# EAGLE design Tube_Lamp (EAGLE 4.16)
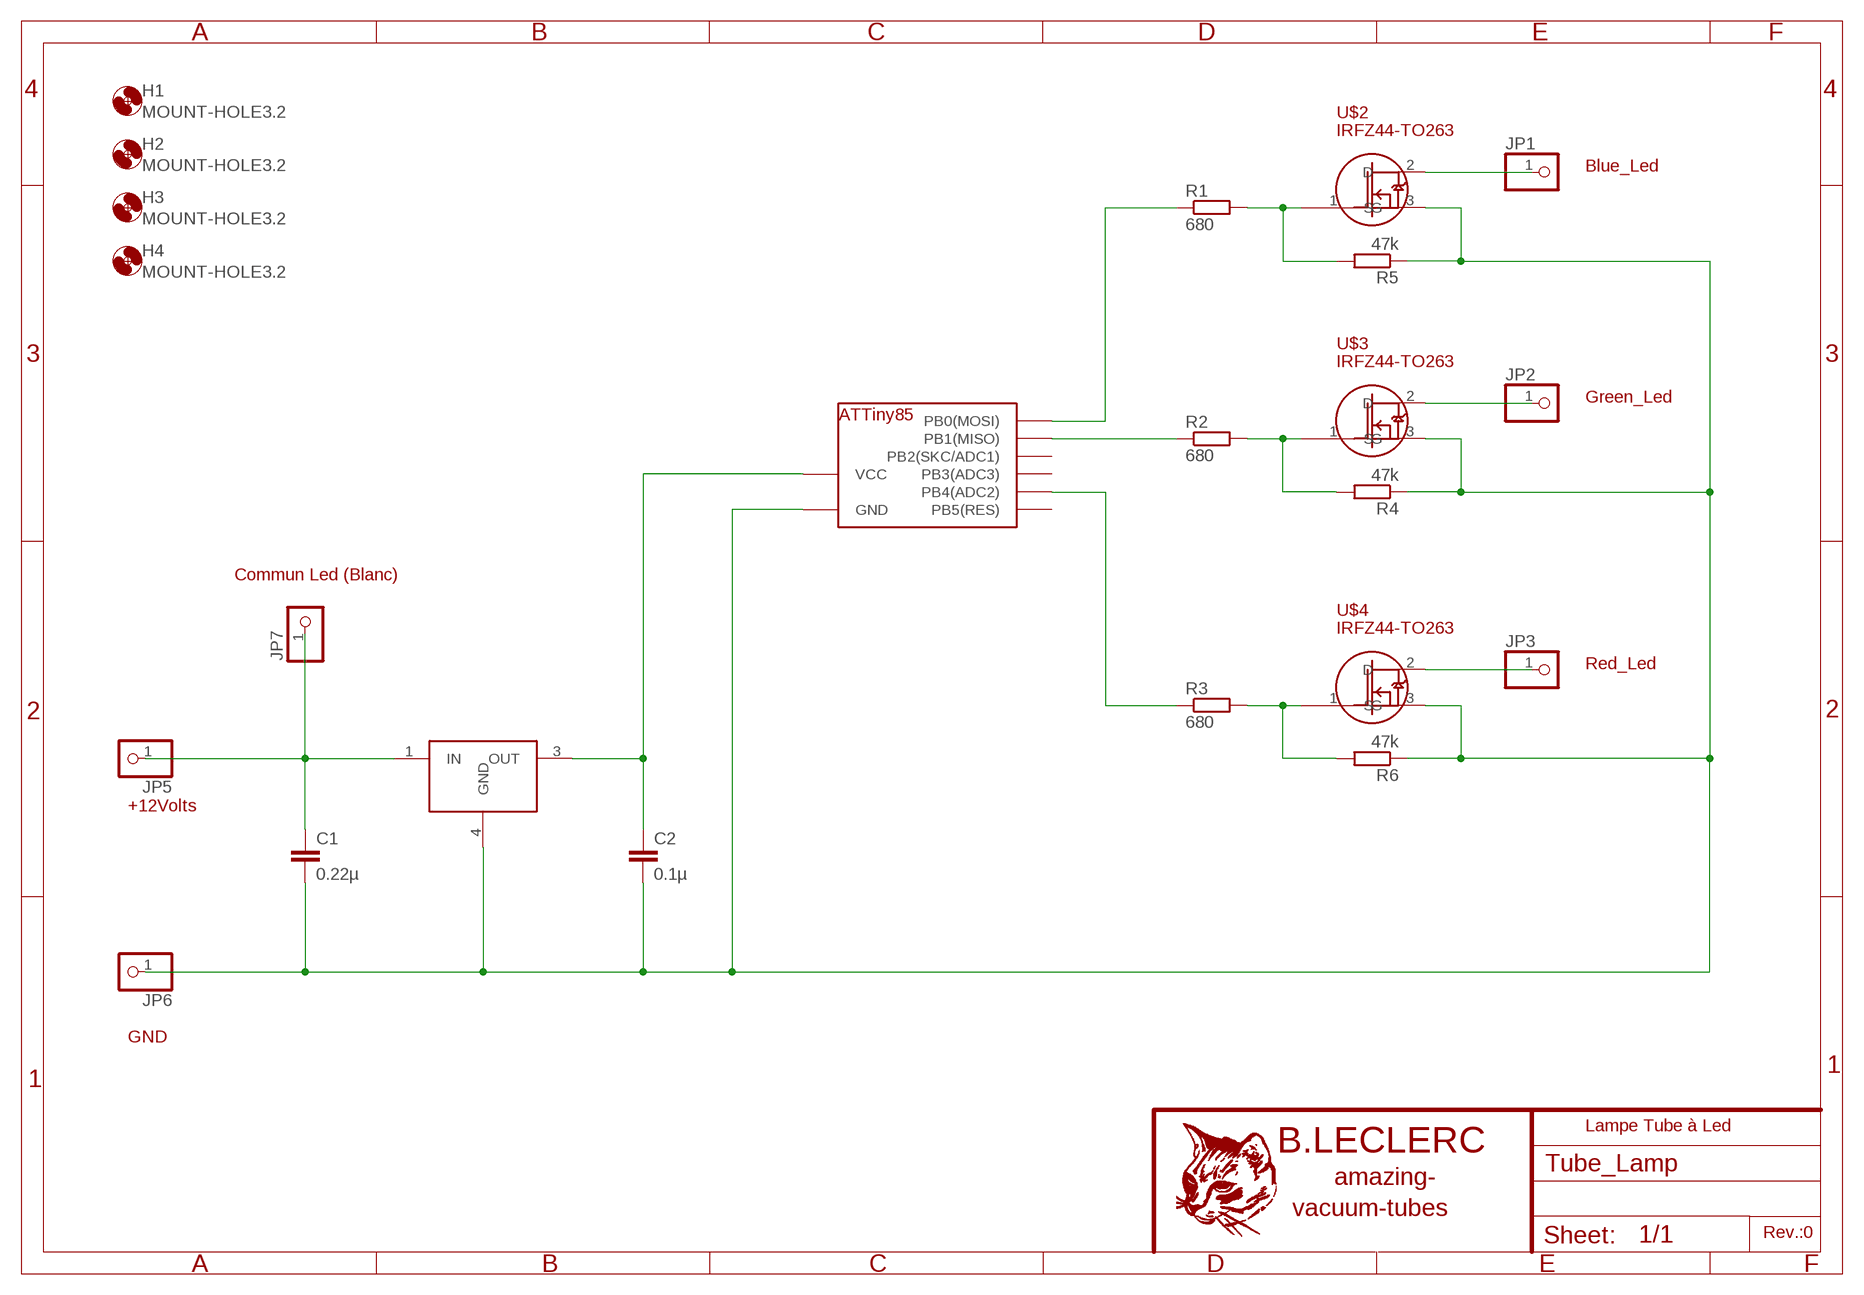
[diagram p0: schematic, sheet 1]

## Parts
C1  0.22µ  C-EUC1206K  [C1206K]
C2  0.1µ  C-EUC1206K  [C1206K]
H1  MOUNT-HOLE3.2  [3,2]
H2  MOUNT-HOLE3.2  [3,2]
H3  MOUNT-HOLE3.2  [3,2]
H4  MOUNT-HOLE3.2  [3,2]
JP1  PINHD-1X1  [1X01]
JP2  PINHD-1X1  [1X01]
JP3  PINHD-1X1  [1X01]
JP5  PINHD-1X1  [1X01]
JP6  PINHD-1X1  [1X01]
JP7  PINHD-1X1  [1X01]
R1  680  R-EU_M1206  [M1206]
R2  680  R-EU_M1206  [M1206]
R3  680  R-EU_M1206  [M1206]
R4  47k  R-EU_M1206  [M1206]
R5  47k  R-EU_M1206  [M1206]
R6  47k  R-EU_M1206  [M1206]
U1  7805  MINI78XX  [DPACK]
U$2  IRFZ44-TO263  [TO263]
U$3  IRFZ44-TO263  [TO263]
U$4  IRFZ44-TO263  [TO263]
U$5  ATTINY85  [DIL08]

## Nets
GND: C1.2 C2.2 JP6.1 R4.1 R5.1 R6.1 U1.4(GND) U$2.3(S) U$3.3(S) U$4.3(S) U$5.4(GND)
N$1: R1.1 U$5.5(PB0(MOSI))
N$2: R2.1 U$5.6(PB1(MISO))
N$3: R3.1 U$5.3(PB4(ADC2))
N$4: R1.2 R5.2 U$2.1(G)
N$5: R2.2 R4.2 U$3.1(G)
N$6: R3.2 R6.2 U$4.1(G)
N$7: JP1.1 U$2.2(D)
N$8: JP2.1 U$3.2(D)
N$9: JP3.1 U$4.2(D)
N$14: C1.1 JP5.1 JP7.1 U1.1(IN)
N$15: C2.1 U1.3(OUT) U$5.8(VCC)
Unconnected: U$5.1(PB5(RES)) U$5.2(PB3(ADC3)) U$5.7(PB2(SKC/ADC1))

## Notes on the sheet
- Blue_Led
- Green_Led
- Commun Led (Blanc)
- Red_Led
- +12Volts
- GND
- Lampe Tube à Led
- Rev.:0

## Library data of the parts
C1 C2 = rcl:C-EU: CAPACITOR, European symbol
H1-H4 = holes:MOUNT-HOLE: MOUNTING HOLE with drill center marker
JP1-JP3 JP5-JP7 = pinhead:PINHD-1X1: PIN HEADER
R1-R6 = rcl:R-EU_: RESISTOR, European symbol
U1 = v-reg:MINI78XX
U$2-U$4 = transistor-fet:IRFZ44-TO263
U$5 = atmel:ATTINY85

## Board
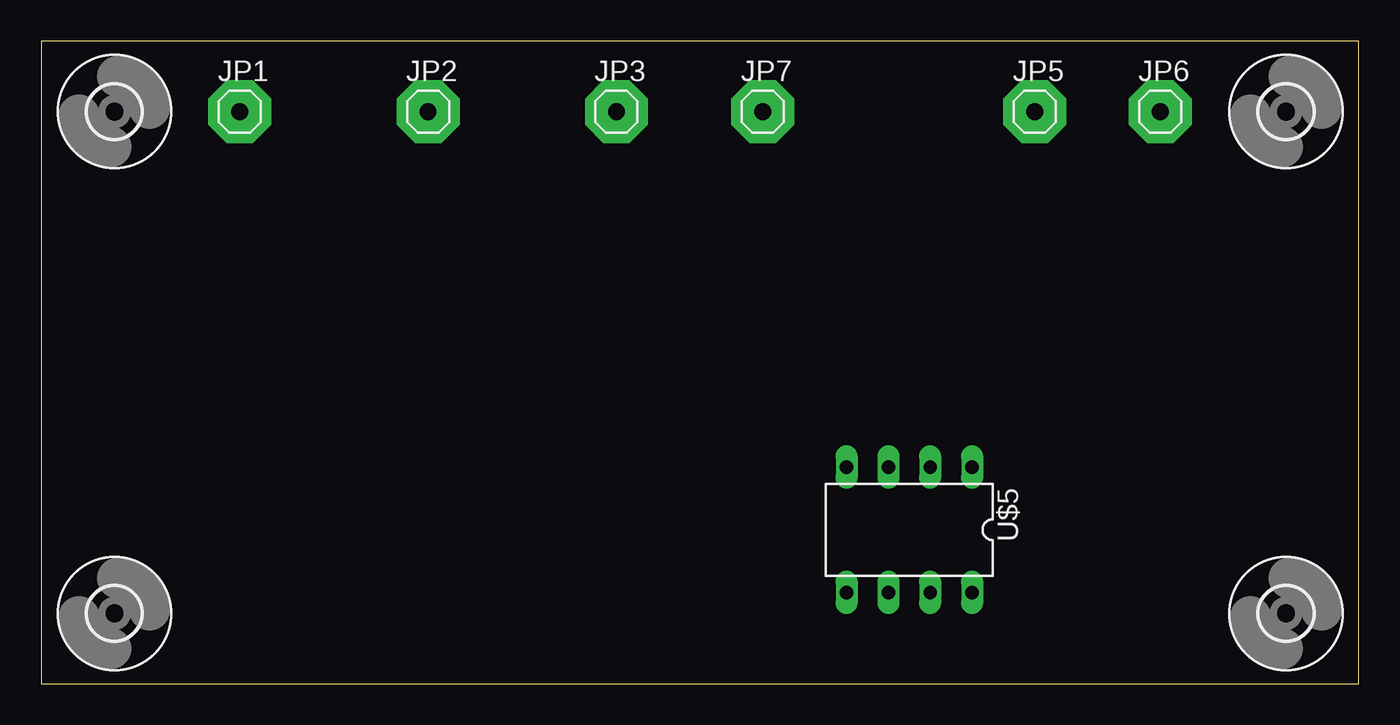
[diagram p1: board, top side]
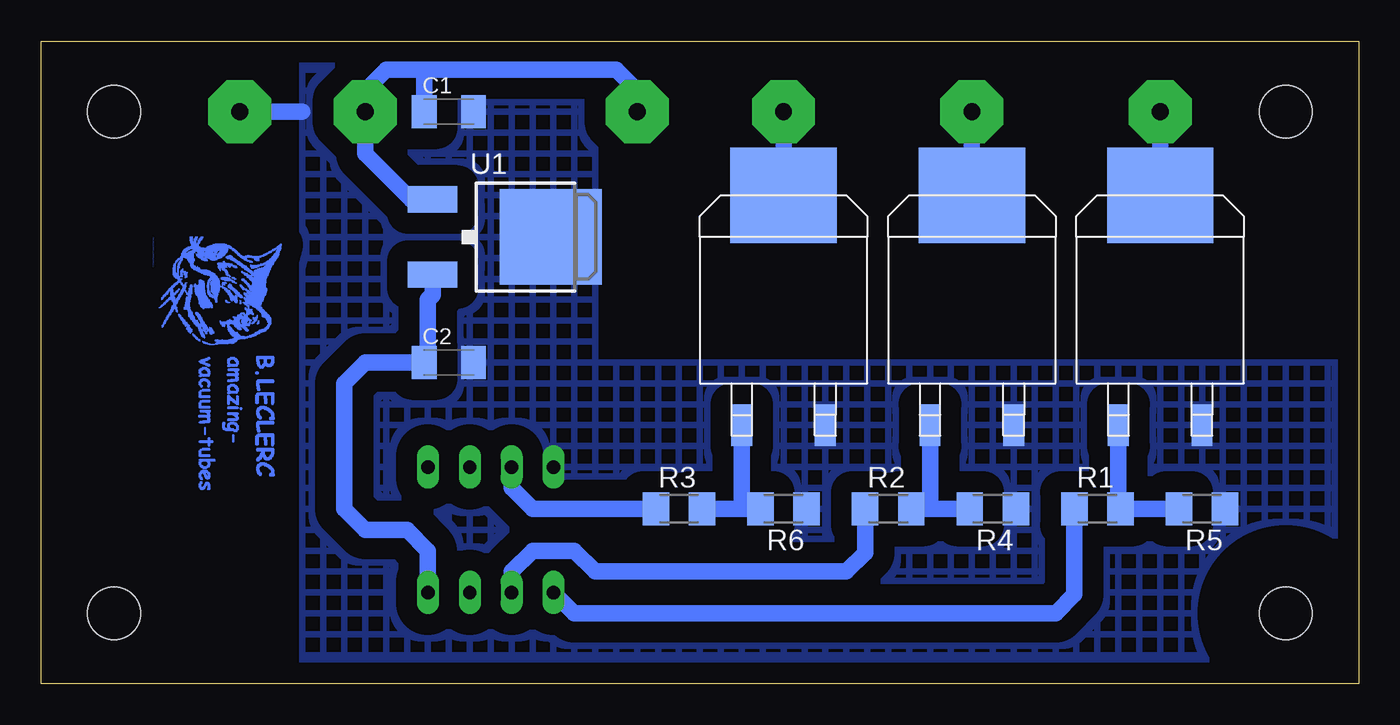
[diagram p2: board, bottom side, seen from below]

Size 79.99 x 39.04 mm. Coordinates in mm from the lower left corner, seen from the top.
Outline: 0,0 79.99,0 79.99,39.04 0,39.04 0,0
Copper layers (1*16): Top 0.035mm / dielectric 1.5mm / Bottom 0.035mm
Design rules "default": minimum track width 10mil, minimum drill 24mil, track to track 8mil, track to pad 8mil, pad to pad 8mil, via to via 8mil, smd to smd 8mil, copper to edge 40mil, drill to drill 8mil, minimum pad ring 10mil, minimum via ring 8mil, stop-mask expansion 4mil, vias tented up to drill 0mil, thermal gap 10mil

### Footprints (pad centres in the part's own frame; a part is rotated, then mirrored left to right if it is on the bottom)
C1206K = smd 1.5 x 2: 1 -1.5,0; 2 1.5,0
3,2 = hole 3.2: 0,0
1X01 = drill 1.016 octagon: 1 0,0
M1206 = smd 1.6 x 2: 1 -1.4,0; 2 1.4,0
DPACK = smd 1.6 x 3: 1 -2.28,-4.8; 3 2.28,-4.8 | smd 5.8 x 6.2: 4 0,2.38
TO263 = smd 2.54 x 1.27: 1 0,2.54; 3 0,-2.54 | smd 3.251 x 6.452: 2 15.24,0; P$3 12.7,0
DIL08 = drill 0.813 long: 1 -3.81,-3.81; 2 -1.27,-3.81; 3 1.27,-3.81; 4 3.81,-3.81; 5 3.81,3.81; 6 1.27,3.81; 7 -1.27,3.81; 8 -3.81,3.81

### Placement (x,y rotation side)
C1  55.24,34.76 0 bottom
C2  55.24,19.52 0 bottom
H1  4.44,4.28 0 top
H2  4.44,34.76 0 top
H3  75.56,4.28 0 top
H4  75.56,34.76 0 top
JP1  12.06,34.76 0 top
JP2  23.49,34.76 0 top
JP3  34.92,34.76 0 top
JP5  60.32,34.76 0 top
JP6  67.94,34.76 0 top
JP7  43.81,34.76 0 top
R1  15.87,10.63 0 bottom
R2  28.57,10.63 0 bottom
R3  41.27,10.63 0 bottom
R4  22.22,10.63 180 bottom
R5  9.52,10.63 180 bottom
R6  34.92,10.63 180 bottom
U1  51.43,27.14 270 bottom
U$2  12.06,15.71 90 bottom
U$3  23.49,15.71 90 bottom
U$4  34.92,15.71 90 bottom
U$5  52.7,9.36 180 top
U$6  [CHAT]  73.02,27.14 270 bottom

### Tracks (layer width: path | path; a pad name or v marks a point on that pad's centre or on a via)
GND  (via drill 0.5 pad 1.27, 0.5 pad 3.81)
  Bottom 1.016: 64.13,34.76 JP6.1
  other vias: 67.94,34.76 48.89,13.17
  pour Bottom (isolate 1.27, no thermals, hatched): 0.63,19.52 46.35,19.52 46.35,38.57 64.13,38.57 64.13,0.47 0.63,0.47
N$1
  Bottom 1.016: R1.1 17.27,5.42 18.41,4.28 47.62,4.28 U$5.5
N$2
  Bottom 1.016: R2.1 29.97,7.96 31.11,6.82 46.35,6.82 47.62,8.09 50.16,8.09 51.43,6.82 U$5.6
N$3
  Bottom 1.016: R3.1 50.16,10.63 51.43,11.9 U$5.3
N$4
  Bottom 1.016: U$2.1 14.6,10.63 R1.2 R5.2 10.79,10.63
N$5
  Bottom 1.016: U$3.1 26.03,10.63 R2.2 | R2.2 27.3,10.63 | 23.49,10.63 R4.2 R2.2
N$6
  Bottom 1.016: 36.19,10.63 R6.2 37.46,10.63 | 37.46,10.63 R3.2 | 37.46,10.63 U$4.1
N$7
  Bottom 1.016: U$2.2 JP1.1
N$8
  Bottom 1.016: U$3.2 JP2.1
N$9
  Bottom 1.016: U$4.2 JP3.1
N$10  (via drill 0.5 pad 3.81)
  other vias: 12.06,34.76
N$11  (via drill 0.5 pad 3.81)
  other vias: 34.92,34.76
N$12  (via drill 0.5 pad 3.81)
  other vias: 43.81,34.76
N$14
  Bottom 1.016: JP7.1 43.81,36.03 45.08,37.3 56.51,37.3 | 56.51,37.3 59.05,37.3 60.32,36.03 JP5.1 60.32,32.22 57.52,29.42 U1.1 | C1.1 56.74,37.07 56.51,37.3
N$15
  Bottom 1.016: U1.3 56.23,23.61 56.51,23.33 56.51,19.52 C2.1 60.32,19.52 61.59,18.25 61.59,10.63 60.32,9.36 57.78,9.36 56.51,8.09 U$5.8
N$16  (via drill 0.5 pad 3.81)
  other vias: 60.32,34.76
N$17  (via drill 0.5 pad 3.81)
  other vias: 23.49,34.76
N$18  (via drill 0.5 pad 1.27)
  other vias: 53.97,5.55
N$19  (via drill 0.5 pad 1.27)
  other vias: 56.51,5.55
N$20  (via drill 0.5 pad 1.27)
  other vias: 48.89,5.55
N$21  (via drill 0.5 pad 1.27)
  other vias: 51.43,5.55
N$22  (via drill 0.5 pad 1.27)
  other vias: 56.51,13.17
N$23  (via drill 0.5 pad 1.27)
  other vias: 53.97,13.17
N$25  (via drill 0.5 pad 1.27)
  other vias: 51.43,13.17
